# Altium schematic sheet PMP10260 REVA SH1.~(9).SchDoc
size 431 x 279 mm; Date: Not shown in title block; ApprovedBy: Not shown in title block; CheckedBy: Not shown in title block; Author: Not shown in title block; CompanyName: Not shown in title block; Engineer: Not shown in title block; Organization: Not shown in title block; Address1: Not shown in title block; Address2: Not shown in title block; Address3: Not shown in title block; Address4: Not shown in title block; DocumentNumber: 1; Revision: Use project parameter SCH_Rev; SheetNumber: 1; SheetTotal: 3; PageSetup: Record=PageOptions|CenterHorizontal=True|CenterVertical=True|PrintScale=1.00|XCorrection=1.00|YCorrection=1.00|PrintKind=0|BorderSize=5000000|LeftOffset=0|BottomOffset=0|Orientation=2|PaperLength=1000|PaperWidth=1000|Scale=100|PaperSource=15|PrintQuality=600|MediaType=1|DitherType=10|PaperKind=Letter|PrintScaleMode=1
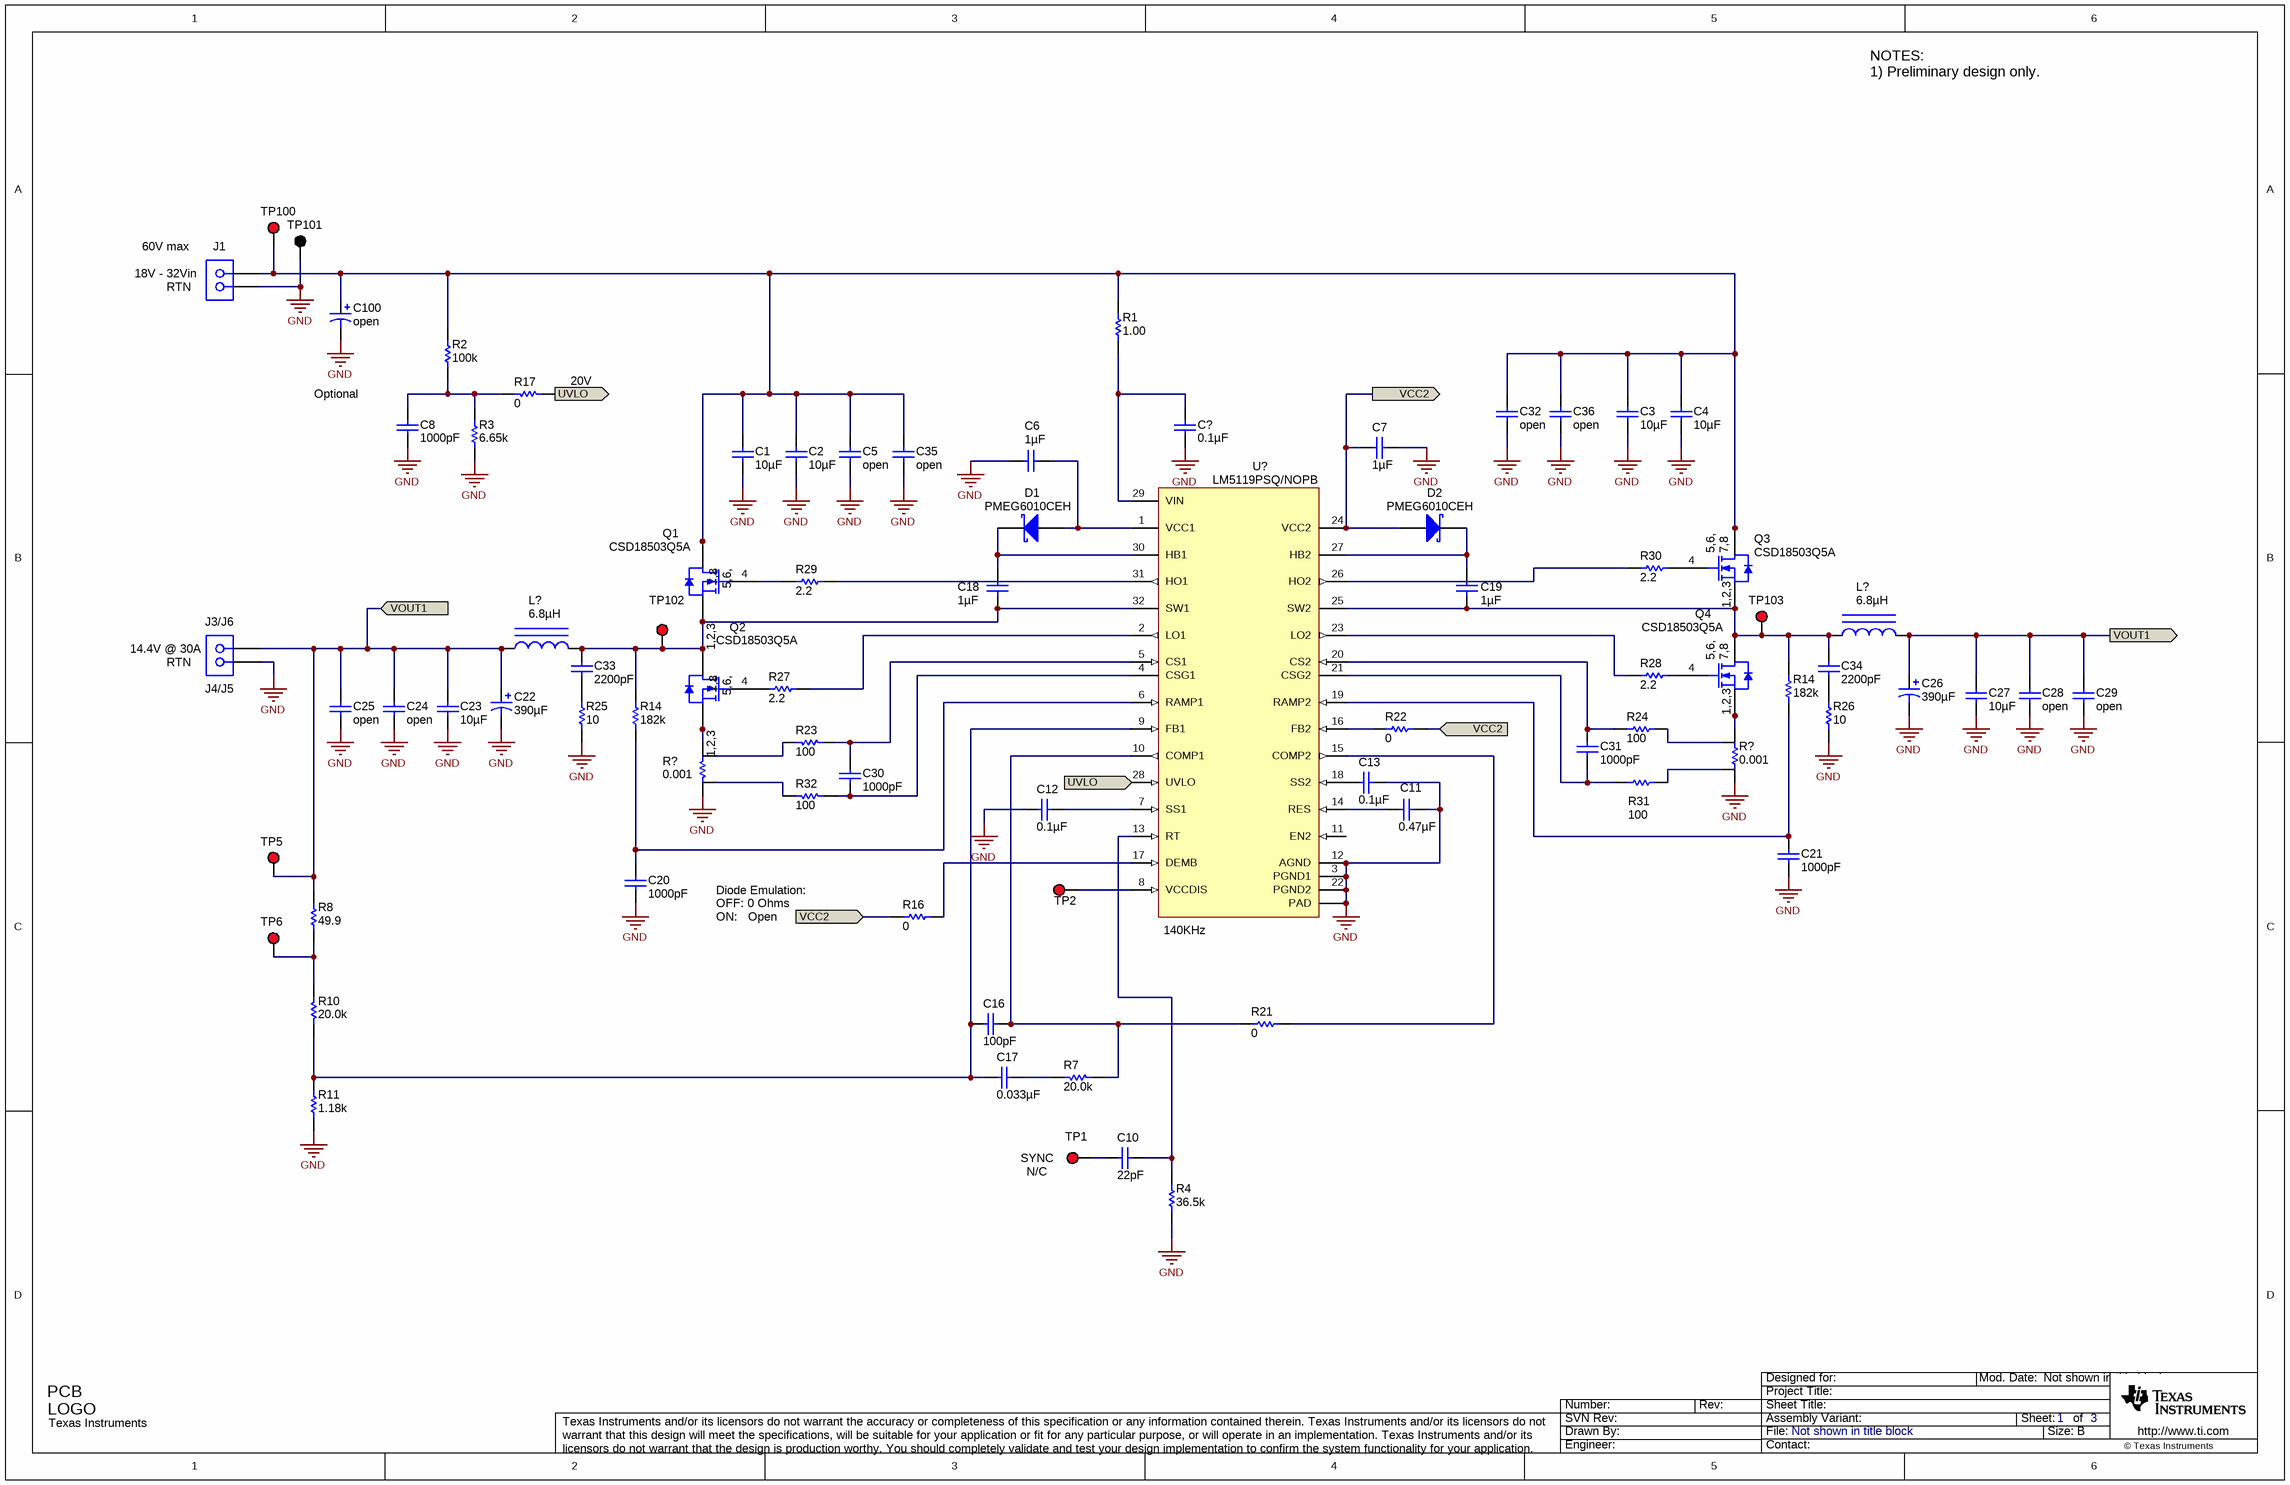
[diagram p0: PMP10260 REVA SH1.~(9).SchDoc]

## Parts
(Parts that share a designator on the sheet are numbered #1, #2 ... from top to bottom, then left to right.)
C1  ValueDisplayed: 10µF  [1210]  (hidden comment: C3225X5R1H106M250AB)
C2  ValueDisplayed: 10µF  [1210]  (hidden comment: C3225X5R1H106M250AB)
C3  ValueDisplayed: 10µF  [1210]  (hidden comment: C3225X5R1H106M250AB)
C4  ValueDisplayed: 10µF  [1210]  (hidden comment: C3225X5R1H106M250AB)
C5  ValueDisplayed: open  [1210]
C6  ValueDisplayed: 1µF  [0603L]  (hidden comment: C1608X7R1E105K080AB)
C7  ValueDisplayed: 1µF  [0603L]  (hidden comment: C1608X7R1E105K080AB)
C8  ValueDisplayed: 1000pF  [0603]  (hidden comment: C1608C0G1H102J)
C10  ValueDisplayed: 22pF  [0603]  (hidden comment: C1608C0G1H220J)
C11  ValueDisplayed: 0.47µF  [0603L]  (hidden comment: C0603C474K4RACTU)
C12  ValueDisplayed: 0.1µF  [0603L]  (hidden comment: C1608X7R1H104K)
C13  ValueDisplayed: 0.1µF  [0603L]  (hidden comment: C1608X7R1H104K)
C16  ValueDisplayed: 100pF  [0603]  (hidden comment: C1608C0G1H101J)
C17  ValueDisplayed: 0.033µF  [0603]  (hidden comment: GRM188R71H333KA61D)
C18  ValueDisplayed: 1µF  [0603L]  (hidden comment: C1608X7R1E105K080AB)
C19  ValueDisplayed: 1µF  [0603L]  (hidden comment: C1608X7R1E105K080AB)
C20  ValueDisplayed: 1000pF  [0603]  (hidden comment: C1608C0G1H102J)
C21  ValueDisplayed: 1000pF  [0603]  (hidden comment: C1608C0G1H102J)
C22  ValueDisplayed: 390µF  [SM_RADIAL_8MM]  (hidden comment: 20SVPF390M)
C23  ValueDisplayed: 10µF  [1210L]  (hidden comment: GMK325AB7106MM-T)
C24  ValueDisplayed: open  [1210]
C25  ValueDisplayed: open  [1210]
C26  ValueDisplayed: 390µF  [SM_RADIAL_8MM]  (hidden comment: 20SVPF390M)
C27  ValueDisplayed: 10µF  [1210L]  (hidden comment: GMK325AB7106MM-T)
C28  ValueDisplayed: open  [1210]
C29  ValueDisplayed: open  [1210]
C30  ValueDisplayed: 1000pF  [0603]  (hidden comment: C1608C0G1H102J)
C31  ValueDisplayed: 1000pF  [0603]  (hidden comment: C1608C0G1H102J)
C32  ValueDisplayed: open  [1210]
C33  ValueDisplayed: 2200pF  [0603L]  (hidden comment: C0603C222K5RAC)
C34  ValueDisplayed: 2200pF  [0603L]  (hidden comment: C0603C222K5RAC)
C35  ValueDisplayed: open  [1210]
C36  ValueDisplayed: open  [1210]
C100  ValueDisplayed: open  [SM_RADIAL_8MM]
C?  ValueDisplayed: 0.1µF  [0805_HV]  (hidden comment: C2012X7R2A104K)
D1  PMEG6010CEH  [SOD-123F]
D2  PMEG6010CEH  [SOD-123F]
J1  ED120/2DS  [CONN_ED120-2DS]  (value not drawn)
J2  ED120/2DS  [CONN_ED120-2DS]  (value not drawn)
L?#1  ValueDisplayed: 6.8µH  [SER2915]  (hidden comment: SER2915H-682KL)
L?#2  ValueDisplayed: 6.8µH  [SER2915]  (hidden comment: SER2915H-682KL)
Logo1  Texas Instruments  [TI_Stacked_Overlay_Small]  (no BOM)
Q1  CSD18503Q5A  [TRANS_NexFET_Q5A]
Q2  CSD18503Q5A  [TRANS_NexFET_Q5A]
Q3  CSD18503Q5A  [TRANS_NexFET_Q5A]
Q4  CSD18503Q5A  [TRANS_NexFET_Q5A]
R1  value 1.00  [0805_HV]  (hidden comment: CRCW08051R00FKEA)
R2  value 100k  [0603L]  (hidden comment: CRCW0603100KFKEA)
R3  value 6.65k  [0603L]  (hidden comment: CRCW06036K65FKEA)
R4  value 36.5k  [0603]  (hidden comment: CRCW060336K5FKEA)
R7  value 20.0k  [0603]  (hidden comment: CRCW060320K0FKEA)
R8  value 49.9  [0603]  (hidden comment: CRCW060349R9FKEA)
R10  value 20.0k  [0603L]  (hidden comment: CRCW060320K0FKEA)
R11  value 1.18k  [0603]  (hidden comment: CRCW06031K18FKEA)
R14#1  value 182k  [0603]  (hidden comment: CRCW0603182KFKEA)
R14#2  value 182k  [0603]  (hidden comment: CRCW0603182KFKEA)
R16  value 0  [0603L]  (hidden comment: CRCW06030000Z0EA)
R17  value 0  [0603]  (hidden comment: CRCW06030000Z0EA)
R21  value 0  [0603L]  (hidden comment: CRCW06030000Z0EA)
R22  value 0  [0603L]  (hidden comment: CRCW06030000Z0EA)
R23  value 100  [0603L]  (hidden comment: RC0603FR-07100RL)
R24  value 100  [0603L]  (hidden comment: RC0603FR-07100RL)
R25  value 10  [2010M]  (hidden comment: CRCW201010R0JNEFHP)
R26  value 10  [2010M]  (hidden comment: CRCW201010R0JNEFHP)
R27  value 2.2  [0603L]  (hidden comment: CRCW06032R20JNEA)
R28  value 2.2  [0603L]  (hidden comment: CRCW06032R20JNEA)
R29  value 2.2  [0603L]  (hidden comment: CRCW06032R20JNEA)
R30  value 2.2  [0603L]  (hidden comment: CRCW06032R20JNEA)
R31  value 100  [0603L]  (hidden comment: RC0603FR-07100RL)
R32  value 100  [0603L]  (hidden comment: RC0603FR-07100RL)
R?#1  value 0.001  [1224]  (hidden comment: LVK25R001FER)
R?#2  value 0.001  [1224]  (hidden comment: LVK25R001FER)
TP1  5010  [Keystone5010]  (value not drawn)
TP2  5010  [Keystone5010]  (value not drawn)
TP5  5010  [Keystone5010]  (value not drawn)
TP6  5010  [Keystone5010]  (value not drawn)
TP100  5010  [Keystone5010]  (value not drawn)
TP101  5011  [Keystone5011]  (value not drawn)
TP102  5010  [Keystone5010]  (value not drawn)
TP103  5010  [Keystone5010]  (value not drawn)
U?  LM5119PSQ/NOPB  [RTV0032A]

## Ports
UVLO, VCC2, VOUT1

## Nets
GND: C1.2 C2.2 C3.2 C4.2 C5.2 C6.2 C7.2 C8.2 C11.1 C12.2 C13.1 C20.2 C21.2 C22.2(-) C23.2 C24.2 C25.2 C26.2(-) C27.2 C28.2 C29.2 C32.2 C35.2 C36.2 C100.2(-) C?.2 J1.2 J2.2 R3.1 R4.1 R11.1 R25.1 R26.1 R?#1.1 R?#2.1 TP101.1 U?.3(PGND1) U?.12(AGND) U?.22(PGND2) U?.33(PAD)
UVLO: R17.1 U?.28(UVLO) ; port UVLO
VCC2: C7.1 D2.2(A) R16.1 R22.2 U?.24(VCC2) ; port VCC2
VOUT1: C22.1(+) C23.1 C24.1 C25.1 C26.1(+) C27.1 C28.1 C29.1 J2.1 L?#1.2 L?#2.1 R8.2 TP5.1 ; port VOUT1
NetC1_1: C1.1 C2.1 C3.1 C4.1 C5.1 C32.1 C35.1 C36.1 C100.1(+) J1.1 Q1.5(D) Q1.6(D) Q1.7(D) Q1.8(D) Q1.9(D) Q3.5(D) Q3.6(D) Q3.7(D) Q3.8(D) Q3.9(D) R1.1 R2.2 TP100.1
NetC6_1: C6.1 D1.2(A) U?.1(VCC1)
NetC8_1: C8.1 R2.1 R3.2 R17.2
NetC10_1: C10.1 R4.2 U?.13(RT)
NetC10_2: C10.2 TP1.1
NetC11_2: C11.2 U?.14(RES)
NetC12_1: C12.1 U?.7(SS1)
NetC13_2: C13.2 U?.18(SS2)
NetC16_1: C16.1 R7.1 R21.1 U?.10(COMP1)
NetC16_2: C16.2 C17.2 R10.1 R11.2 U?.9(FB1)
NetC17_1: C17.1 R7.2
NetC18_1: C18.1 D1.1(K) U?.30(HB1)
NetC18_2: C18.2 C33.1 L?#2.2 Q1.1(S) Q1.2(S) Q1.3(S) Q2.5(D) Q2.6(D) Q2.7(D) Q2.8(D) Q2.9(D) R14#2.2 TP102.1 U?.32(SW1)
NetC19_1: C19.1 D2.1(K) U?.27(HB2)
NetC19_2: C19.2 C34.1 L?#1.1 Q3.1(S) Q3.2(S) Q3.3(S) Q4.5(D) Q4.6(D) Q4.7(D) Q4.8(D) Q4.9(D) R14#1.2 TP103.1 U?.25(SW2)
NetC20_1: C20.1 R14#2.1 U?.6(RAMP1)
NetC21_1: C21.1 R14#1.1 U?.19(RAMP2)
NetC30_1: C30.1 R23.1 U?.5(CS1)
NetC30_2: C30.2 R32.1 U?.4(CSG1)
NetC31_1: C31.1 R24.1 U?.20(CS2)
NetC31_2: C31.2 R31.1 U?.21(CSG2)
NetC33_2: C33.2 R25.2
NetC34_2: C34.2 R26.2
NetC?_1: C?.1 R1.2 U?.29(VIN)
NetQ1_4: Q1.4(G) R29.1
NetQ2_1: Q2.1(S) Q2.2(S) Q2.3(S) R?#2.2
NetQ2_4: Q2.4(G) R27.1
NetQ3_4: Q3.4(G) R30.2
NetQ4_1: Q4.1(S) Q4.2(S) Q4.3(S) R?#1.2
NetQ4_4: Q4.4(G) R28.2
NetR8_1: R8.1 R10.2 TP6.1
NetR16_2: R16.2 U?.17(DEMB)
NetR21_2: R21.2 U?.15(COMP2)
NetR22_1: R22.1 U?.16(FB2)
NetR23_2: R23.2 R?#2.4
NetR24_2: R24.2 R?#1.4
NetR27_2: R27.2 U?.2(LO1)
NetR28_1: R28.1 U?.23(LO2)
NetR29_2: R29.2 U?.31(HO1)
NetR30_1: R30.1 U?.26(HO2)
NetR31_2: R31.2 R?#1.3
NetR32_2: R32.2 R?#2.3
NetTP2_1: TP2.1 U?.8(VCCDIS)

Not connected (* = marked no-connect by the designer): U? 11(EN2)

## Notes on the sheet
- NOTES:
  1) Preliminary design only.
- (near J1) 18V - 32Vin
- (near J1) 60V max
- (near J1) RTN
- (near J1) J1
- Optional
- (near R17) 20V
- (near J2) J3/J6
- (near J2) 14.4V @ 30A
- (near J2) RTN
- (near J2) J4/J5
- Diode Emulation:
- OFF: 0 Ohms
- ON:   Open
- (near U?) 140KHz
- (near TP1) SYNC
- (near TP1) N/C

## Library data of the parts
C1-C4 = C3225X7R1H335M: CAP, CERM, 10uF, 50V, +/-20%, X5R, 1210; Manufacturer: TDK; Polarized: N; CompType: Capacitor; U/M: EA; Cap_F: 0.0000033; Tolerance_%: 20; Value1: Unknown; VDC_V: 50; TaMin_C: -55; TaMax_C: 125
C5 C24 C25 C28 C29 C32 C35 C36 = C3225X7R1H335M: CAP, CERM, open, 1210; Manufacturer: TDK; Polarized: N; CompType: Capacitor; Value: 10uF; U/M: EA; Cap_F: 0.0000033; Tolerance_%: 20; Value1: Unknown; VDC_V: 50; Value2: 50V; TempCo: X5R; TaMin_C: -55; TaMax_C: 125
C6 C7 C18 C19 = C1608X7R1E105K080AB: CAP, CERM, 1uF, 25V, +/-10%, X7R, 0603; Manufacturer: TDK; Polarized: N; CompType: Capacitor; U/M: EA; Cap_F: 0.000001; Tolerance_%: 10; Value1: Unknown; VDC_V: 25; TaMin_C: -55; TaMax_C: 125; Cap_Case: 0603
C8 C20 C21 C30 C31 = C1608C0G1H102J: CAP, CERM, 1000pF, 50V, +/-5%, C0G/NP0, 0603; Manufacturer: TDK; Polarized: N; CompType: Capacitor; U/M: EA; Cap_F: 0.000000001; Tolerance_%: 5; ESR_Ohm: 0.0563; Value1: 0.0563 ohm; VDC_V: 50; TaMin_C: -55; TaMax_C: 125
C10 = C1608C0G1H220J: CAP, CERM, 22pF, 50V, +/-5%, C0G/NP0, 0603; Manufacturer: TDK; Polarized: N; CompType: Capacitor; U/M: EA; Cap_F: 0.000000000022; Tolerance_%: 5; ESR_Ohm: 0.3882; Value1: 0.3882 ohm; VDC_V: 50; TaMin_C: -55; TaMax_C: 125
C11 = C0603C474K4RACTU: CAP, CERM, 0.47uF, 16V, +/-10%, X7R, 0603; Manufacturer: Kemet; Polarized: N; CompType: Capacitor; U/M: EA; Cap_F: 0.00000047; Tolerance_%: 10; Value1: Unknown; VDC_V: 16; TaMin_C: -55; TaMax_C: 125; Cap_Case: 0603
C12 C13 = C1608X7R1H104K: CAP, CERM, 0.1uF, 50V, +/-10%, X7R, 0603; Manufacturer: TDK; Polarized: N; CompType: Capacitor; U/M: EA; Cap_F: 0.0000001; Tolerance_%: 10; ESR_Ohm: 0.017; Value1: 0.017 ohm; VDC_V: 50; TaMin_C: -55; TaMax_C: 125; Cap_Case: 0603
C16 = C1608C0G1H101J: CAP, CERM, 100pF, 50V, +/-5%, C0G/NP0, 0603; Manufacturer: TDK; Polarized: N; CompType: Capacitor; U/M: EA; Cap_F: 0.0000000001; Tolerance_%: 5; ESR_Ohm: 0.1679; Value1: 0.1679 ohm; VDC_V: 50; TaMin_C: -55; TaMax_C: 125
C17 = GRM188R71H333KA61D: CAP, CERM, 0.033uF, 50V, +/-10%, X7R, 0603; Manufacturer: MuRata; Polarized: N; CompType: Capacitor; U/M: EA; Cap_F: 0.000000033; Tolerance_%: 10; Value1: Unknown; VDC_V: 50; TaMin_C: -55; TaMax_C: 125
C22 C26 = 20SVP100M: CAP, OS-CON, 390uF, 20V, +/-20%, 0.014 ohm, 8x10 SMD; Manufacturer: Sanyo; Polarized: Y; CompType: Capacitor; U/M: EA; Cap_F: 0.0001; Tolerance_%: 20; ESR_Ohm: 0.024; IRMS_A: 3.32; TaMin_C: -55; TaMax_C: 105; Cap_Case: 8.3x8.3x11.9
C23 C27 = GMK325AB7106MM-T: CAP, CERM, 10uF, 35V, +/-20%, X7R, 1206; Manufacturer: Taiyo Yuden; Polarized: N; CompType: Capacitor; U/M: EA; Cap_F: 0.00001; Tolerance_%: 20; Value1: Unknown; VDC_V: 35; TaMin_C: -55; TaMax_C: 125; Cap_Case: 1210
C33 C34 = C0603C222K5RAC: CAP, CERM, 2200pF, 50V, +/-10%, X7R, 0603; Manufacturer: Kemet; Polarized: N; CompType: Capacitor; U/M: EA; Cap_F: 0.0000000022; Tolerance_%: 10; Value1: Unknown; VDC_V: 50; TaMin_C: -55; TaMax_C: 125; Cap_Case: 0603
C100 = 20SVP100M: CAP, OS-CON, open; Manufacturer: Sanyo; Polarized: Y; CompType: Capacitor; Value: 82uF; U/M: EA; Cap_F: 0.0001; Tolerance_%: 20; Value1: 0.020 ohm; VDC_V: 35; Value2: 35V; ESR_Ohm: 0.024; IRMS_A: 3.32; TaMin_C: -55; TaMax_C: 105; Cap_Case: 8.3x8.3x11.9
C? = C2012X7R2A104K: CAP, CERM, 0.1uF, 100V, +/-10%, X7R, 0805; Manufacturer: TDK; Polarized: N; CompType: Capacitor; U/M: EA; Cap_F: 0.0000001; Tolerance_%: 10; ESR_Ohm: 0.0158; Value1: 0.0158 ohm; VDC_V: 100; TaMin_C: -55; TaMax_C: 125; Cap_Case: 0805
D1 D2 = PMEG6010CEH,115: Diode, Schottky, 60V, 1A, SOD-123F; Manufacturer: NXP Semiconductor; U/M: EA; Vf_V: 0.57; Value2: 0.57V; Io_A: 1; Vr_V: 60; TJmax_C: 150
J1 J2 = ED120/2DS: TERMINAL BLOCK 5.08MM VERT 2POS; Manufacturer: On-Shore Technology, Inc.; U/M: EA
L?#1 L?#2 = SER2915H-682KL: Inductor, Shielded E Core, Ferrite, 6.8uH, 30A, 0.00186 ohm, SMD; Manufacturer: Coilcraft; Ind_H: 6.8E-6; Imax_A: 30; Irms: 30A @ 40C rise; Isat: 36.2A @ 30% inductance drop; U/M: EA
Logo1 = TI_Logo: Texas Instrument Corporate Signature; SymbolCreator: codlsc
Q1-Q4 = CSD18501Q5A: MOSFET, N-CH, 40V, 3.4 milliohm, SON 5x6mm; Manufacturer: Texas Instruments; Alternate Manufacturer: None; U/M: EA; ChType: N; VdsMax_V: 40; Value1: 0.0034 ohm; Rdson45_Ohm: 0.0043; Value2: 20 nC; QgTyp_nC: 20; IdsMax_A: 22
R1 = CRCW08051R00FKEA: RES, 1.00 ohm, 1%, 0.125W, 0805; Manufacturer: Vishay-Dale; CompType: Resistor; Res_ohm: 1; Value_Code: 1R00; Power_W: 0.125; VDC_V: 150; TempCo: 100 ppm/C; EIA_Code: E96; U/M: EA
R2 = CRCW0603100KFKEA: RES, 100k ohm, 1%, 0.1W, 0603; Manufacturer: Vishay-Dale; CompType: Resistor; Res_ohm: 100000; Tolerance_%: 1; Power_W: 0.1; VDC_V: 75; TempCo: 100 ppm/C; EIA_Code: E96; U/M: EA
R3 = CRCW06036K65FKEA: RES, 6.65k ohm, 1%, 0.1W, 0603; Manufacturer: Vishay-Dale; CompType: Resistor; Res_ohm: 6650; Value_Code: 6k65; Tolerance_%: 1; Power_W: 0.1; VDC_V: 75; TempCo: 100 ppm/C; EIA_Code: E96; U/M: EA
R4 = CRCW060336K5FKEA: RES, 36.5k ohm, 1%, 0.1W, 0603; Manufacturer: Vishay-Dale; CompType: Resistor; Res_ohm: 36500; Value_Code: 36k5; Tolerance_%: 1; Power_W: 0.1; VDC_V: 75; TempCo: 100 ppm/C; EIA_Code: E96; U/M: EA
R7 R10 = CRCW060320K0FKEA: RES, 20.0k ohm, 1%, 0.1W, 0603; Manufacturer: Vishay-Dale; CompType: Resistor; Res_ohm: 20000; Value_Code: 20k0; Tolerance_%: 1; Power_W: 0.1; VDC_V: 75; TempCo: 100 ppm/C; EIA_Code: E96; U/M: EA
R8 = CRCW060349R9FKEA: RES, 49.9 ohm, 1%, 0.1W, 0603; Manufacturer: Vishay-Dale; CompType: Resistor; Value_Code: 49R9; Tolerance_%: 1; Power_W: 0.1; VDC_V: 75; TempCo: 100 ppm/C; EIA_Code: E96; U/M: EA
R11 = CRCW06031K18FKEA: RES, 1.18k ohm, 1%, 0.1W, 0603; Manufacturer: Vishay-Dale; CompType: Resistor; Res_ohm: 1180; Value_Code: 1k18; Tolerance_%: 1; Power_W: 0.1; VDC_V: 75; TempCo: 100 ppm/C; EIA_Code: E96; U/M: EA
R14#1 R14#2 = CRCW0603182KFKEA: RES, 182k ohm, 1%, 0.1W, 0603; Manufacturer: Vishay-Dale; CompType: Resistor; Res_ohm: 182000; Tolerance_%: 1; Power_W: 0.1; VDC_V: 75; TempCo: 100 ppm/C; EIA_Code: E96; U/M: EA
R16 R17 R21 R22 = CRCW06030000Z0EA: RES, 0 ohm, 5%, 0.1W, 0603; Manufacturer: Vishay-Dale; CompType: Resistor; Value_Code: 0000; Tolerance_%: 5; Power_W: 0.1; VDC_V: 75; TempCo: 200 ppm/C; EIA_Code: E24; U/M: EA
R23 R24 R31 R32 = RC0603FR-07100RL: RES, 100 ohm, 1%, 0.1W, 0603; Manufacturer: Yageo America; CompType: Resistor; Value_Code: 100R; Tolerance_%: 1; Power_W: 0.1; VDC_V: 150; TempCo: 200 ppm/C; EIA_Code: E96; U/M: EA
R25 R26 = CRCW20101R00JNEFHP: RES, 10 ohm, 5%, 1W, 2010; Manufacturer: Vishay-Dale; CompType: Resistor; Res_ohm: 1; Value_Code: 1R00; Tolerance_%: 5; VDC_V: 400; TempCo: 200 ppm/C; EIA_Code: E24; U/M: EA
R27-R30 = CRCW06032R20JNEA: RES, 2.2 ohm, 5%, 0.1W, 0603; Manufacturer: Vishay-Dale; CompType: Resistor; Value_Code: 2R20; Tolerance_%: 5; Power_W: 0.1; VDC_V: 75; TempCo: 200 ppm/C; EIA_Code: E24; U/M: EA
R?#1 R?#2 = LVK25R001FER: RES, 0.001 ohm, 1%, 2W, 1224; Manufacturer: Ohmite; CompType: Resistor; Value_Code: R001; Tolerance_%: 1; Power_W: 2; TempCo: 300 ppm/C; EIA_Code: E96; U/M: EA
TP1 TP2 TP5 TP6 TP100 TP102 TP103 = 5010: Test Point, Multipurpose, Red, TH; Manufacturer: Keystone; CompType: Test Point Loop; U/M: EA
TP101 = 5011: Test Point, Multipurpose, Black, TH; Manufacturer: Keystone; CompType: Test Point Loop; U/M: EA
U? = LM5119PSQ/NOPB: LM5119/LM5119Q Wide Input Range Dual Synchronous Buck Controller, RTV0032A; Alternate Manufacturer: None; Manufacturer: Texas Instruments; SymbolCreator: a0411947; CompType: IC; U/M: EA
